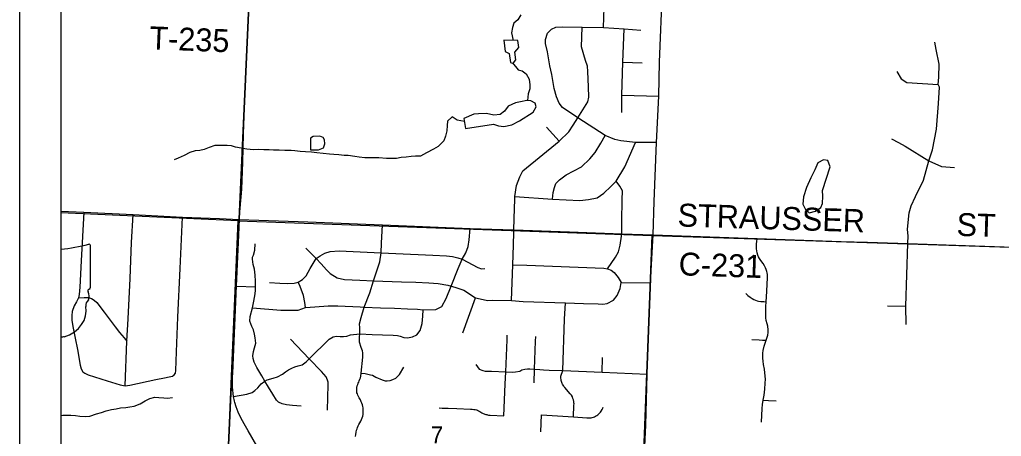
# Model space of a CAD drawing. Extents: x 0 to 34, y 0 to 22.
# Drawn here: x 2.735 to 5.169, y 19.503 to 20.536 of the extents above; entities that cross this region are included whole.
import ezdxf

# ---------------------------------------------------------------- set-up
doc = ezdxf.new("R2010")
doc.units = 0
for name, color, linetype in [('GM_X_Corporation', 7, 'Continuous'), ('GM_X_Corporation_Text', 7, 'Continuous'), ('GM_X_County_Road', 7, 'Continuous'), ('GM_X_County_Road_Text', 7, 'Continuous'), ('GM_X_Minor_Lake', 7, 'Continuous'), ('GM_X_Minor_River', 7, 'Continuous'), ('GM_X_Section_Text', 7, 'Continuous'), ('GM_X_Township_Road', 7, 'Continuous'), ('GM_X_Township_Road_Text', 7, 'Continuous'), ('SH_Data', 7, 'Continuous')]:
    doc.layers.add(name, color=color, linetype=linetype)

msp = doc.modelspace()

# ---------------------------------------------------------------- linework, layer by layer
at = {"layer": 'GM_X_Corporation'}
for points in [[(7.1023, 20.9204), (2.837, 20.9204), (2.837, 14.1204), (9.637, 14.1204), (9.637, 20.9204), (9.4036, 20.9204), (9.4022, 20.8667), (9.2273, 20.8723), (9.1354, 20.8749), (9.124, 20.8753), (8.9858, 20.878), (8.9676, 20.8785), (8.8663, 20.881), (8.6259, 20.8892), (8.5535, 20.8914), (8.5421, 20.8915), (8.4667, 20.8934), (8.0602, 20.9055), (7.9522, 20.9084), (7.1104, 20.9188)], [(3.3169, 20.9204), (2.837, 20.9204), (2.837, 14.9888), (3.0725, 14.9816), (3.0874, 15.351), (3.0879, 15.3623), (3.0883, 15.3712), (3.1072, 15.7483), (3.1177, 16.2414), (3.14, 16.6736), (3.1852, 17.7826), (3.1864, 17.8248), (3.233, 19.0394), (3.2586, 19.6098), (3.2623, 19.6596), (3.2721, 19.8755), (3.2728, 19.892), (3.2744, 19.9301), (3.2774, 20.0014), (3.2794, 20.0412), (3.3026, 20.5526), (3.3089, 20.7046), (3.3168, 20.9187)], [(2.837, 20.0568), (2.837, 19.0523), (3.2335, 19.0353), (3.277, 20.0368)], [(4.3035, 20.0005), (4.2642, 18.9963), (3.2335, 19.0353), (3.277, 20.0368)], [(4.3035, 20.0005), (5.3173, 19.9675), (5.2829, 18.9603), (4.2642, 18.9963)]]:
    msp.add_lwpolyline(points, close=True, dxfattribs=at)
msp.add_lwpolyline([(7.1023, 20.9204), (3.3169, 20.9204), (3.3168, 20.9187), (3.3089, 20.7046), (3.3026, 20.5526), (3.2794, 20.0412), (3.2774, 20.0014), (3.2744, 19.9301), (3.2728, 19.892), (3.2721, 19.8755), (3.2623, 19.6596), (3.2586, 19.6098), (3.233, 19.0394), (3.1864, 17.8248)], dxfattribs=at)
at = {"layer": 'GM_X_Corporation_Text'}
msp.add_line((2.837, 19.9663), (2.837, 19.7481), dxfattribs=at)
msp.add_lwpolyline([(2.9102, 19.8711), (2.9102, 19.8711), (2.9103, 19.8711), (2.9103, 19.976)], dxfattribs=at)
for centre, major_axis, start_param, end_param in [((2.7929, 20.2437), (0.3495, 0), 4.839168, 5.042369), ((2.9066, 19.9762), (0.00367, 0), 6.197627, 7.989034), ((2.9094, 19.8634), (0.00568, 0), 1.883978, 3.671073), ((2.9063, 19.8707), (0.00393, 0), 5.05454, 6.418171), ((2.9234, 19.8273), (0.0248, 0), 2.387724, 3.262537), ((2.8733, 19.8502), (0.0341, 0), 5.934695, 6.695948), ((2.8124, 19.814), (0.0874, 0), 5.101753, 6.440018), ((2.8493, 19.7111), (0.0479, 0), 1.647645, 1.829477)]:
    msp.add_ellipse(centre, major_axis=major_axis, ratio=0.8, start_param=start_param, end_param=end_param, dxfattribs=at)
at = {"layer": 'GM_X_County_Road'}
for points in [[(3.2688, 19.5867), (3.268, 19.5898), (3.2655, 19.6012), (3.2642, 19.6089), (3.2628, 19.6257), (3.2623, 19.642), (3.2626, 19.659), (3.2723, 19.875), (3.273, 19.8915), (3.2746, 19.9296), (3.2776, 20.0009), (3.2796, 20.0406), (3.2855, 20.1153), (3.288, 20.1827), (3.29, 20.2522), (3.2943, 20.3595), (3.3028, 20.552), (3.3091, 20.704), (3.317, 20.9182), (3.3171, 20.9204)], [(2.837, 20.0609), (2.8938, 20.0582), (3.0163, 20.0526), (3.139, 20.0464), (3.2305, 20.0423), (3.2796, 20.0406)], [(3.2796, 20.0406), (3.4491, 20.0341), (3.6345, 20.0266), (3.8523, 20.0182), (3.9606, 20.0142), (4.0981, 20.0093), (4.2276, 20.0046), (4.3055, 20.0023)], [(4.3055, 20.0023), (4.5632, 19.9931), (4.7721, 19.986), (4.8367, 19.9838), (4.937, 19.981), (5.3186, 19.9678)], [(3.3231, 19.4791), (3.3014, 19.5168), (3.2918, 19.5336), (3.2835, 19.5489), (3.2771, 19.5624), (3.272, 19.5756), (3.2688, 19.5867)]]:
    msp.add_lwpolyline(points, dxfattribs=at)
at = {"layer": 'GM_X_Minor_Lake'}
for points in [[(3.9356, 20.4846), (3.9386, 20.4569), (3.9485, 20.4517), (3.9518, 20.4293), (3.956, 20.4279), (3.9598, 20.4287), (3.965, 20.4359), (3.9629, 20.4549), (3.9727, 20.4664), (3.9698, 20.4839)], [(3.9698, 20.4839), (3.9356, 20.4846)], [(3.8407, 20.2659), (3.9098, 20.2761), (3.9224, 20.2725), (3.9357, 20.2707), (3.9554, 20.2747), (3.9743, 20.2844), (4.0079, 20.3061), (4.0157, 20.3191), (4.0129, 20.3289), (4.0026, 20.3345), (3.9927, 20.3352), (3.9764, 20.332), (3.9643, 20.3292), (3.9458, 20.3214), (3.9372, 20.3091), (3.9266, 20.3006), (3.9107, 20.2986), (3.8924, 20.3026), (3.8726, 20.302), (3.8609, 20.3014), (3.8363, 20.2905)], [(3.8363, 20.2905), (3.8407, 20.2659)], [(3.4564, 20.2131), (3.4758, 20.2129), (3.4887, 20.218), (3.492, 20.2275), (3.4911, 20.2378), (3.4876, 20.2438), (3.4789, 20.2468), (3.4629, 20.2462), (3.4565, 20.2416)], [(3.4565, 20.2416), (3.4564, 20.2131)], [(4.7449, 20.1705), (4.7391, 20.1868), (4.728, 20.1882), (4.7141, 20.1804), (4.7063, 20.1629), (4.6962, 20.1434), (4.6862, 20.1193), (4.6781, 20.0968), (4.6768, 20.0786), (4.683, 20.0646), (4.6926, 20.0571), (4.7081, 20.0611), (4.7213, 20.0699), (4.7258, 20.0802), (4.7264, 20.0981), (4.7258, 20.1125)], [(4.7258, 20.1125), (4.7449, 20.1705)]]:
    msp.add_lwpolyline(points, dxfattribs=at)
at = {"layer": 'GM_X_Minor_River'}
for points in [[(3.9779, 20.5474), (3.97, 20.5348), (3.9602, 20.5267), (3.9573, 20.5164), (3.9544, 20.5031), (3.9583, 20.4841)], [(3.9572, 20.4281), (3.971, 20.4109), (3.9809, 20.4084), (3.9905, 20.4013), (3.9979, 20.3877), (3.9995, 20.3736), (3.9996, 20.3638), (3.9956, 20.3515), (3.994, 20.3351)], [(3.8377, 20.283), (3.8196, 20.2862), (3.8074, 20.2948), (3.7961, 20.284), (3.7951, 20.273), (3.7937, 20.2597), (3.7904, 20.2467), (3.7867, 20.2353), (3.7728, 20.2211), (3.7608, 20.2149), (3.7434, 20.2056), (3.7287, 20.197), (3.7161, 20.1969), (3.7059, 20.1964), (3.6933, 20.1951), (3.6812, 20.1939), (3.6691, 20.1918), (3.6444, 20.1916), (3.6257, 20.1929), (3.6155, 20.1931), (3.6025, 20.1934), (3.5912, 20.1929), (3.5771, 20.1943), (3.566, 20.1964), (3.5493, 20.1985), (3.5394, 20.1992), (3.5261, 20.2005), (3.5143, 20.2015), (3.5033, 20.2022), (3.4877, 20.2035), (3.4717, 20.2053), (3.4588, 20.207), (3.4436, 20.208), (3.4306, 20.209), (3.4173, 20.21), (3.4078, 20.211), (3.3926, 20.2112), (3.3782, 20.2118), (3.3641, 20.2121), (3.3538, 20.2127), (3.3405, 20.213), (3.3261, 20.2136), (3.3147, 20.2131), (3.298, 20.2148), (3.2839, 20.2173), (3.2702, 20.2198), (3.2599, 20.2227), (3.2492, 20.2237), (3.2329, 20.2239), (3.2185, 20.2238), (3.2045, 20.2183), (3.1927, 20.2136), (3.1814, 20.2116), (3.17, 20.21), (3.1567, 20.2064), (3.1427, 20.199), (3.1276, 20.192), (3.1178, 20.1877)], [(2.9854, 19.5731), (2.9983, 19.5743), (3.0078, 19.576), (3.0188, 19.578), (3.0336, 19.5838), (3.0464, 19.5908), (3.0578, 19.5963), (3.0703, 19.5998), (3.0798, 19.5995), (3.0923, 19.5982), (3.1018, 19.5975), (3.1143, 19.5995)], [(2.837, 19.5547), (2.842, 19.5555), (2.8515, 19.5556), (2.8618, 19.5554), (2.8732, 19.5547), (2.8846, 19.5526), (2.8987, 19.5516), (2.9089, 19.5528), (2.9256, 19.5583), (2.9377, 19.5623), (2.9494, 19.5658), (2.9623, 19.569), (2.9744, 19.5714), (2.9854, 19.5731)]]:
    msp.add_lwpolyline(points, dxfattribs=at)
at = {"layer": 'GM_X_Township_Road'}
for p, q in [((4.1827, 20.5162), (4.1855, 20.5973)), ((4.2302, 20.4298), (4.278, 20.4288)), ((4.228, 20.3484), (4.3194, 20.3462)), ((4.073, 20.2342), (4.0416, 20.2688)), ((3.4702, 19.9438), (3.4449, 19.9695)), ((3.2723, 19.875), (3.3198, 19.873)), ((3.8341, 19.7591), (3.8652, 19.8465)), ((4.8869, 19.8265), (4.932, 19.8258)), ((4.1792, 19.6622), (4.18, 19.6984)), ((3.5806, 19.6516), (3.582, 19.6594)), ((4.0269, 19.5139), (4.0292, 19.5565))]:
    msp.add_line(p, q, dxfattribs=at)
for points in [[(4.2439, 18.4919), (4.2655, 18.9966), (4.2737, 19.2276), (4.2759, 19.2794), (4.2802, 19.3808), (4.2827, 19.4257), (4.2875, 19.5306), (4.2904, 19.6566), (4.2961, 19.799), (4.2987, 19.8835), (4.3055, 20.0023), (4.3079, 20.0845), (4.3139, 20.2312), (4.3194, 20.3462), (4.3214, 20.4305), (4.3286, 20.6129), (4.3409, 20.9092), (4.3413, 20.9204)], [(3.9625, 20.0891), (3.9629, 20.0972), (3.9666, 20.1242), (3.9747, 20.1456), (3.9828, 20.1612), (4.073, 20.2342), (4.0963, 20.2575), (4.1076, 20.2744), (4.1192, 20.292), (4.1441, 20.3318), (4.1463, 20.3436), (4.1456, 20.3688), (4.1434, 20.4072), (4.1428, 20.4199), (4.1377, 20.4343), (4.1277, 20.4684), (4.1295, 20.5166)], [(4.3139, 20.2312), (4.262, 20.2314), (4.2258, 20.2351), (4.211, 20.2385), (4.187, 20.2488), (4.1192, 20.292), (4.0808, 20.3178), (4.073, 20.3282), (4.0656, 20.3441), (4.0601, 20.3652), (4.0545, 20.3999), (4.0497, 20.4208), (4.0434, 20.4556), (4.0386, 20.4763), (4.0386, 20.4859), (4.044, 20.5024), (4.0532, 20.5116), (4.0645, 20.517), (4.0801, 20.5181), (4.1295, 20.5166), (4.1827, 20.5162), (4.2341, 20.5126), (4.2749, 20.5096)], [(4.2276, 20.3056), (4.228, 20.3484), (4.2302, 20.4298), (4.2341, 20.5126)], [(4.9328, 19.7799), (4.932, 19.8258), (4.937, 19.981), (4.9378, 19.9999), (4.9363, 20.0152), (4.9379, 20.0324), (4.9402, 20.0568), (4.9453, 20.0745), (4.9564, 20.0975), (4.9756, 20.1381), (4.9889, 20.1855), (4.9985, 20.2127), (5.0081, 20.2637), (5.0133, 20.328), (5.0155, 20.3678), (5.0122, 20.3748), (5.0141, 20.393), (5.0148, 20.4248), (5.0074, 20.4617), (5.0039, 20.4795)], [(4.9094, 20.4066), (4.9205, 20.3885), (4.9349, 20.38), (5.0122, 20.3748)], [(3.9629, 20.0972), (4.0559, 20.0902), (4.1242, 20.0876), (4.1453, 20.0894), (4.1667, 20.0939), (4.183, 20.1057), (4.2004, 20.122), (4.2139, 20.1354), (4.2351, 20.1707), (4.262, 20.2314)], [(4.0559, 20.0902), (4.0581, 20.1068), (4.061, 20.1197), (4.0647, 20.1297), (4.0736, 20.1385), (4.0899, 20.1511), (4.1091, 20.1607), (4.1279, 20.171), (4.149, 20.1906), (4.1619, 20.2065), (4.1763, 20.229), (4.187, 20.2488)], [(4.8967, 20.2399), (4.9137, 20.231), (4.9307, 20.2221), (4.9889, 20.1855), (5.0209, 20.1719), (5.0526, 20.1689)], [(4.1928, 19.9183), (4.2123, 19.9469), (4.2197, 19.9601), (4.224, 19.9769), (4.2273, 19.9988), (4.2276, 20.0046), (4.2277, 20.0365), (4.2291, 20.0891), (4.2293, 20.1114), (4.2231, 20.1227), (4.2139, 20.1354)], [(3.9604, 20.0092), (3.9606, 20.0142), (3.9617, 20.0687), (3.9625, 20.0891)], [(2.8938, 20.0582), (2.8874, 19.9377), (2.8843, 19.8722), (2.8828, 19.8541), (2.8811, 19.8462), (2.8759, 19.8362), (2.8705, 19.8265), (2.8656, 19.8126), (2.8645, 19.8021), (2.8647, 19.7899), (2.8678, 19.7706), (2.8729, 19.746), (2.8782, 19.7177), (2.8853, 19.6791), (2.8874, 19.6704), (2.8914, 19.663)], [(2.8914, 19.663), (2.8963, 19.659), (2.9049, 19.6553), (2.9206, 19.6502), (2.9521, 19.6406), (2.9845, 19.6306), (2.9968, 19.6284), (3.0081, 19.6298), (3.0723, 19.6439), (3.0941, 19.6477), (3.1054, 19.65), (3.1136, 19.652), (3.1183, 19.6549), (3.1215, 19.6596), (3.1226, 19.6661), (3.124, 19.712), (3.1273, 19.7983), (3.1327, 19.9188), (3.139, 20.0464)], [(2.9968, 19.6284), (3.0011, 19.7384), (3.0038, 19.7939), (3.009, 19.8936), (3.0127, 19.9835), (3.0163, 20.0526)], [(3.3127, 19.8212), (3.3829, 19.8152), (3.4059, 19.8152), (3.4257, 19.8157), (3.4433, 19.8218), (3.4669, 19.824), (3.4999, 19.8262), (3.5241, 19.8262), (3.5796, 19.8234), (3.5895, 19.823), (3.6293, 19.8212), (3.6646, 19.8204), (3.6965, 19.819), (3.7211, 19.8179), (3.7352, 19.8166), (3.7667, 19.8174), (3.7814, 19.8244), (3.7925, 19.8443), (3.8048, 19.875), (3.822, 19.9186), (3.8322, 19.9418), (3.8413, 19.9575), (3.847, 19.9731), (3.8498, 19.9896), (3.8523, 20.0182)], [(3.6311, 19.9577), (3.6323, 19.9815), (3.6345, 20.0266)], [(3.9546, 19.8391), (3.9574, 19.9282), (3.9593, 19.977), (3.9604, 20.0092)], [(4.5742, 19.5376), (4.5757, 19.572), (4.5764, 19.5817), (4.5784, 19.5924), (4.5805, 19.6049), (4.5826, 19.62), (4.5837, 19.6349), (4.5839, 19.6447), (4.5835, 19.6523), (4.5818, 19.6692), (4.5796, 19.6809), (4.5781, 19.6891), (4.5778, 19.6963), (4.5774, 19.7015), (4.5775, 19.7051), (4.5775, 19.7088), (4.5782, 19.7156), (4.581, 19.7266), (4.5859, 19.7409), (4.5878, 19.7465), (4.5897, 19.7535), (4.591, 19.7605), (4.5911, 19.7669), (4.59, 19.7759), (4.5884, 19.782), (4.586, 19.79), (4.585, 19.7966), (4.5848, 19.8033), (4.5854, 19.825), (4.5859, 19.8361), (4.5872, 19.8618), (4.5883, 19.881), (4.589, 19.8947), (4.5888, 19.904), (4.5885, 19.9077), (4.5877, 19.9114), (4.5862, 19.9161), (4.5843, 19.9207), (4.5817, 19.9256), (4.5784, 19.9309), (4.5726, 19.939), (4.5696, 19.9437), (4.5672, 19.948), (4.5655, 19.952), (4.5639, 19.9574), (4.5629, 19.9622), (4.5622, 19.9678), (4.5619, 19.9734), (4.562, 19.9809), (4.5625, 19.9852), (4.5632, 19.9931)], [(3.4328, 19.5779), (3.4111, 19.5791), (3.3962, 19.5806), (3.3855, 19.5838), (3.3769, 19.5873), (3.3717, 19.5921), (3.3631, 19.607), (3.3517, 19.6247), (3.3426, 19.6396), (3.3355, 19.6527), (3.3229, 19.6732), (3.3166, 19.6866), (3.3143, 19.6956), (3.3135, 19.7023), (3.3147, 19.7133), (3.317, 19.7224), (3.3202, 19.7334), (3.319, 19.7468), (3.317, 19.7563), (3.3147, 19.7669), (3.3107, 19.7748), (3.306, 19.7882), (3.3064, 19.7996), (3.3127, 19.8212), (3.3157, 19.8377), (3.3188, 19.856), (3.32, 19.8654), (3.3198, 19.873), (3.32, 19.8872), (3.3193, 19.9026), (3.3169, 19.917), (3.3139, 19.9288), (3.3129, 19.9354), (3.3127, 19.9421), (3.3127, 19.9468), (3.3148, 19.9522), (3.3181, 19.9645), (3.3188, 19.9801)], [(3.3548, 19.8839), (3.3801, 19.8828), (3.3988, 19.8816), (3.4156, 19.8823), (3.4257, 19.885), (3.4363, 19.8913), (3.4454, 19.9003), (3.4554, 19.9184), (3.4702, 19.9438), (3.4801, 19.9499), (3.4918, 19.9569), (3.5049, 19.9612), (3.5268, 19.9625), (3.5963, 19.9595), (3.6311, 19.9577), (3.6673, 19.9559), (3.7595, 19.952), (3.7932, 19.9499), (3.8084, 19.9483), (3.8217, 19.9451), (3.8322, 19.9418), (3.8709, 19.921), (3.8801, 19.9178), (3.8881, 19.9189)], [(3.4702, 19.9438), (3.4823, 19.9301), (3.4961, 19.9152), (3.5049, 19.9064), (3.5219, 19.896), (3.54, 19.8916), (3.5788, 19.8897), (3.6126, 19.8884), (3.6818, 19.8861), (3.7174, 19.885), (3.7492, 19.8834), (3.7729, 19.8812), (3.7965, 19.8773), (3.8048, 19.875), (3.8141, 19.8724), (3.8361, 19.8647), (3.8652, 19.8465), (3.8769, 19.8432), (3.8952, 19.8398), (3.9084, 19.8399), (3.9546, 19.8391), (3.9833, 19.837), (4.0886, 19.8339), (4.1326, 19.8323), (4.1693, 19.831), (4.1806, 19.8305), (4.1916, 19.8324), (4.2075, 19.8405), (4.2165, 19.8516), (4.2235, 19.8693), (4.2263, 19.8838), (4.2987, 19.8835)], [(3.6134, 19.8908), (3.6279, 19.9353), (3.6311, 19.9577)], [(3.9574, 19.9282), (3.9927, 19.9268), (4.1836, 19.92), (4.1928, 19.9183), (4.2014, 19.9147), (4.209, 19.9091), (4.2192, 19.8964), (4.2263, 19.8838)], [(3.5895, 19.823), (3.603, 19.8584), (3.6126, 19.8884), (3.6134, 19.8908)], [(3.4433, 19.8218), (3.4422, 19.8344), (3.4384, 19.8515), (3.4301, 19.874), (3.4257, 19.885)], [(2.8811, 19.8462), (2.8948, 19.847), (2.9057, 19.8473), (2.9133, 19.8448), (2.92, 19.8403), (2.9262, 19.8343), (2.9447, 19.8103), (2.9721, 19.7741), (2.9827, 19.7604), (2.9942, 19.7467), (3.0011, 19.7384)], [(4.5354, 19.8565), (4.5407, 19.8518), (4.5461, 19.8476), (4.5508, 19.8445), (4.5552, 19.8421), (4.5593, 19.8404), (4.5635, 19.839), (4.5672, 19.8382), (4.5728, 19.8374), (4.5802, 19.8366), (4.5859, 19.8361)], [(3.2655, 19.6012), (3.2985, 19.6074), (3.3111, 19.6117), (3.3182, 19.6161), (3.3257, 19.6232), (3.3341, 19.633), (3.3426, 19.6396), (3.3485, 19.6429), (3.3633, 19.6474), (3.3745, 19.6503), (3.3867, 19.657), (3.3938, 19.6629), (3.4013, 19.6673), (3.4095, 19.672), (3.4174, 19.6748), (3.4257, 19.6775), (3.4351, 19.6803), (3.4454, 19.6873), (3.453, 19.695), (3.5025, 19.7437), (3.5127, 19.7492), (3.5202, 19.7507), (3.53, 19.7504), (3.5383, 19.7504), (3.5462, 19.7507), (3.5556, 19.7547), (3.5781, 19.757), (3.6092, 19.7555), (3.6348, 19.7547), (3.6608, 19.7535), (3.6718, 19.7527), (3.6781, 19.7515), (3.6872, 19.7476), (3.697, 19.7468), (3.7088, 19.7496), (3.7194, 19.7547), (3.7277, 19.7653), (3.7332, 19.7822), (3.7348, 19.8008), (3.7352, 19.8166)], [(3.5781, 19.757), (3.5783, 19.7715), (3.5772, 19.7813), (3.5821, 19.7977), (3.5895, 19.823)], [(4.1078, 19.551), (4.1093, 19.5797), (4.1094, 19.5834), (4.1093, 19.5861), (4.1089, 19.5892), (4.1081, 19.5929), (4.1069, 19.5966), (4.1053, 19.6004), (4.1028, 19.6045), (4.1001, 19.608), (4.0865, 19.6236), (4.0852, 19.6252), (4.0838, 19.627), (4.0822, 19.6294), (4.081, 19.6318), (4.0799, 19.6341), (4.079, 19.6365), (4.0783, 19.6387), (4.0777, 19.6413), (4.0772, 19.6441), (4.077, 19.6466), (4.0771, 19.6521), (4.0821, 19.6661), (4.086, 19.7929), (4.0886, 19.8339)], [(3.4981, 19.5676), (3.5001, 19.6306), (3.5001, 19.6373), (3.4985, 19.6421), (3.4946, 19.6507), (3.4836, 19.6633), (3.453, 19.695), (3.4064, 19.7433)], [(3.582, 19.6594), (3.5858, 19.6991), (3.5861, 19.7095), (3.5849, 19.7147), (3.5818, 19.723), (3.5774, 19.736), (3.5772, 19.7487), (3.5781, 19.757)], [(3.7754, 19.5732), (3.7825, 19.5728), (3.7973, 19.5723), (3.8191, 19.5715), (3.8528, 19.5703), (3.8569, 19.5699), (3.8612, 19.5697), (3.8643, 19.5693), (3.8676, 19.5684), (3.87, 19.5676), (3.8725, 19.5662), (3.8756, 19.5645), (3.8781, 19.5631), (3.8809, 19.561), (3.8844, 19.5594), (3.8869, 19.5586), (3.8885, 19.5578), (3.8904, 19.5573), (3.8931, 19.5569), (3.8951, 19.5565), (3.8976, 19.5557), (3.8994, 19.5553), (3.9017, 19.5553), (3.9356, 19.5538), (3.9385, 19.6325), (3.94, 19.6624), (3.9436, 19.7423), (3.944, 19.7535)], [(4.0107, 19.6358), (4.0116, 19.6696), (4.014, 19.7387), (4.0147, 19.7505)], [(4.5502, 19.7426), (4.5685, 19.7419), (4.577, 19.7412), (4.5859, 19.7409)], [(3.582, 19.6594), (3.5916, 19.6582), (3.6045, 19.6553), (3.6097, 19.6544), (3.6178, 19.6498), (3.6334, 19.6429), (3.6415, 19.6403), (3.6458, 19.6403), (3.6533, 19.6414), (3.6605, 19.6434), (3.668, 19.6472), (3.6769, 19.6561), (3.6876, 19.674)], [(3.8658, 19.681), (3.8742, 19.6695), (3.8831, 19.666), (3.8892, 19.664), (3.8949, 19.664), (3.9045, 19.6641), (3.94, 19.6624), (3.958, 19.6617), (3.9646, 19.6624), (3.9751, 19.6647), (3.9797, 19.6673), (3.9873, 19.6696), (3.9939, 19.6699), (3.9995, 19.6699), (4.0116, 19.6696), (4.0248, 19.6686), (4.0337, 19.6679), (4.048, 19.6669), (4.0821, 19.6661), (4.1792, 19.6622), (4.2904, 19.6566)], [(3.5675, 19.5024), (3.5682, 19.5073), (3.5692, 19.5128), (3.5705, 19.5178), (3.5717, 19.5216), (3.5728, 19.5251), (3.5742, 19.5286), (3.5762, 19.5322), (3.5788, 19.5365), (3.5807, 19.5401), (3.5828, 19.5447), (3.5844, 19.549), (3.5857, 19.5531), (3.5864, 19.5571), (3.5868, 19.5609), (3.587, 19.5647), (3.5869, 19.5683), (3.5866, 19.5732), (3.586, 19.5771), (3.5847, 19.5813), (3.5835, 19.5847), (3.5821, 19.5883), (3.5797, 19.593), (3.5768, 19.5982), (3.5748, 19.6014), (3.5734, 19.6048), (3.5725, 19.6078), (3.5713, 19.611), (3.5707, 19.6155), (3.5707, 19.619), (3.5711, 19.6235), (3.5718, 19.6278), (3.5732, 19.6315), (3.5745, 19.6343), (3.5758, 19.637), (3.5769, 19.6401), (3.5787, 19.6447), (3.5799, 19.6482), (3.5806, 19.6516)], [(4.0292, 19.5565), (4.1078, 19.551), (4.1408, 19.5487), (4.1438, 19.5484), (4.1465, 19.5484), (4.1494, 19.5486), (4.1521, 19.549), (4.1547, 19.5496), (4.1576, 19.5504), (4.1602, 19.5514), (4.163, 19.5528), (4.1657, 19.5544), (4.1681, 19.556), (4.1707, 19.5582), (4.1727, 19.5601), (4.1749, 19.5626), (4.177, 19.5655), (4.179, 19.569), (4.1805, 19.5723), (4.1815, 19.5751)], [(4.5784, 19.5924), (4.5914, 19.5919), (4.611, 19.5911)]]:
    msp.add_lwpolyline(points, dxfattribs=at)
at = {"layer": 'SH_Data'}
msp.add_line((2.7349, 21.0001), (2.7349, 14.0001), dxfattribs=at)

# ---------------------------------------------------------------- texts
at = {"layer": 'GM_X_County_Road_Text'}
for s, rotation, p in [('STRAUSSER', 358.1798, (4.3656, 20.0232)), ('ST', 358.2295, (5.0573, 19.9998)), ('C-231', 358.0725, (4.3682, 19.9021))]:
    msp.add_text(s, height=0.05682, rotation=rotation, dxfattribs=at).set_placement(p)
at = {"layer": 'GM_X_Section_Text'}
msp.add_text('7', height=0.0419, rotation=0, dxfattribs=at).set_placement((3.7541, 19.4856))
at = {"layer": 'GM_X_Township_Road_Text'}
msp.add_text('T-235', height=0.05682, rotation=357.7541, dxfattribs=at).set_placement((3.0557, 20.4623))

doc.saveas('drawing.dxf')
